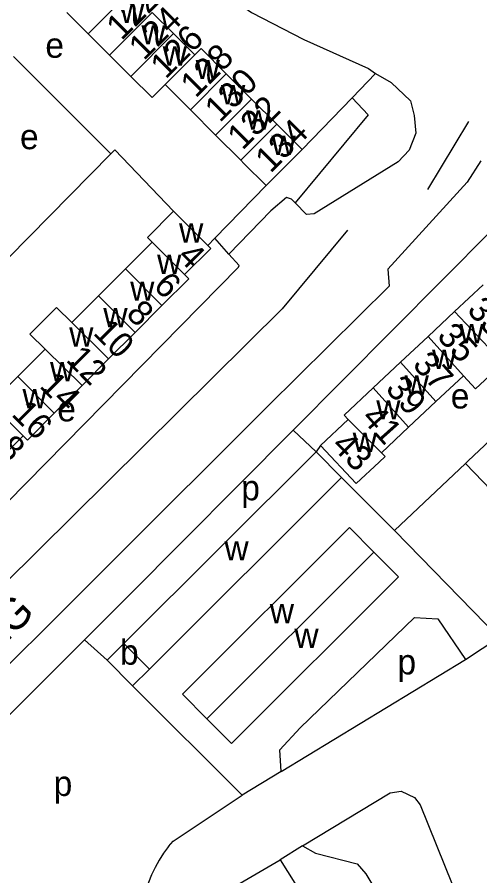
# Model space of a CAD drawing. Extents: x 159261 to 160849, y 382514 to 384534.
# Drawn here: x 160281.9 to 160355.7, y 383033.8 to 383170.7 of the extents above; entities that cross this region are included whole.
import ezdxf

# ---------------------------------------------------------------- set-up
doc = ezdxf.new("R2010")
doc.units = 0
for name, color, linetype in [('BLT_Basislijn', 7, 'Continuous'), ('BLT_Bebouwing', 7, 'Continuous'), ('BLT_Centroide', 7, 'Continuous'), ('BLT_Huisnummer', 7, 'Continuous'), ('BLT_Huisnummer_ tussenligend', 7, 'Continuous'), ('BLT_Onderverdeling_panden', 7, 'Continuous'), ('BLT_Straatnaam', 7, 'Continuous')]:
    doc.layers.add(name, color=color, linetype=linetype)

msp = doc.modelspace()

# ---------------------------------------------------------------- linework, layer by layer
at = {"layer": 'BLT_Basislijn'}
for p, q in [((160296.87, 383148.92), (160281.34, 383164.4)), ((160339.03, 383161.72), (160335.3, 383157.85)), ((160335.3, 383157.85), (160327.34, 383149.59)), ((160353.86, 383154.07), (160347.31, 383143.2)), ((160313.41, 383135.45), (160321.61, 383143.85)), ((160312.31, 383134.31), (160313.41, 383135.45)), ((160315.65, 383132.91), (160313.41, 383135.45)), ((160325.92, 383104.86), (160299.73, 383078.5)), ((160329.56, 383101.41), (160325.92, 383104.86)), ((160330.26, 383102.43), (160329.56, 383101.41)), ((160342.09, 383088.85), (160353.4, 383099.54)), ((160353.4, 383099.54), (160362.12, 383090.42)), ((160333.64, 383097.32), (160342.09, 383088.85)), ((160358.68, 383071.8), (160342.09, 383088.85)), ((160299.73, 383078.5), (160292.66, 383071.45)), ((160292.66, 383071.45), (160224.44, 383003.38)), ((160296.25, 383068.17), (160292.66, 383071.45)), ((160353.4, 383068.31), (160358.68, 383071.8)), ((160324.02, 383050.46), (160353.4, 383068.31)), ((160317.78, 383046.67), (160300.32, 383064.08)), ((160324.02, 383050.46), (160317.78, 383046.67)), ((160327.4, 383038.58), (160323.85, 383036.39)), ((160315.53, 383031.53), (160323.85, 383036.39)), ((160323.85, 383036.39), (160327.34, 383030.79))]:
    msp.add_line(p, q, dxfattribs=at)
for points in [[(160232.88, 383210.68), (160232.16, 383211.37), (160228.59, 383214.89), (160237.6, 383223.81), (160244.03, 383230.11), (160249.64, 383235.64), (160297.74, 383187.93), (160303.17, 383183), (160305.86, 383180.84), (160319.29, 383171.45), (160327.62, 383167.15), (160337.92, 383162.53), (160339.03, 383161.72)], [(160339.03, 383161.72), (160341.54, 383160.27), (160344.6, 383157.34), (160345.2, 383154.99), (160345.45, 383152.22), (160344.38, 383149.48), (160342.63, 383147.63), (160329.26, 383139.35), (160328.06, 383139.21), (160326.23, 383141.08)], [(160335.3, 383157.85), (160337.88, 383155.1), (160326.23, 383141.08)], [(160353.4, 383099.54), (160353.83, 383099.95), (160407.94, 383150.82)], [(160296.87, 383148.92), (160297.47, 383149.52), (160306.86, 383139.76)], [(160229.6, 383079.85), (160257.76, 383109.21), (160296.87, 383148.92)], [(160355.84, 383147.78), (160353.62, 383144.38), (160340.98, 383130.53), (160341.2, 383127.83), (160321.87, 383108.69)], [(160326.23, 383141.08), (160325.63, 383141.7), (160324.86, 383141.92), (160322.37, 383139.8), (160315.65, 383132.91)], [(160363.08, 383142.41), (160357.58, 383136.72), (160325.92, 383104.86)], [(160334.55, 383136.76), (160324.14, 383124.2), (160229.84, 383030.77)], [(160247.61, 383061.63), (160249.56, 383062.08), (160317.22, 383130.85), (160317.32, 383131.11), (160315.65, 383132.91)], [(160203.53, 382990.28), (160202.85, 382990.76), (160202.85, 382993.78), (160211.42, 383003.04), (160240.74, 383031.83), (160241.16, 383032.1), (160244.98, 383032.15), (160245.93, 383032.94), (160321.87, 383108.69)], [(160324.02, 383050.46), (160323.79, 383053.92), (160327.01, 383057.43), (160345.24, 383075.02), (160348.98, 383074.77), (160353.4, 383068.31)], [(160327.4, 383038.58), (160341.36, 383047.07), (160343.11, 383047.32), (160345.27, 383046.33), (160346.13, 383045.12), (160353.93, 383025.89), (160370.26, 382983.18)], [(160306.03, 383038.52), (160306.81, 383039.36), (160317.78, 383046.67)], [(160306.03, 383038.52), (160305.26, 383037.45), (160304.55, 383036.33), (160303.91, 383035.17), (160303.34, 383033.97), (160302.85, 383032.74), (160302.43, 383031.49), (160302.08, 383030.21), (160301.82, 383028.91), (160301.63, 383027.6), (160301.59, 383027.15)], [(160327.4, 383038.58), (160329.45, 383037.45), (160336.14, 383035.73), (160337.5, 383034.16), (160361.73, 382993.94), (160361.67, 382992.6), (160359.41, 382991.26), (160359.25, 382990.43), (160364.88, 382981.05), (160365.71, 382980.62), (160370.26, 382983.18)]]:
    msp.add_lwpolyline(points, dxfattribs=at)
at = {"layer": 'BLT_Bebouwing'}
for p, q in [((160289.85, 383171.43), (160293.24, 383168.04)), ((160306.84, 383168.07), (160303.45, 383171.46)), ((160293.24, 383168.04), (160296.64, 383164.65)), ((160310.24, 383164.68), (160306.84, 383168.07)), ((160296.64, 383164.65), (160300.03, 383161.25)), ((160310.24, 383164.68), (160311.24, 383165.68)), ((160315.26, 383161.66), (160311.24, 383165.68)), ((160319.29, 383157.64), (160315.26, 383161.66)), ((160305.51, 383159.95), (160309.53, 383155.93)), ((160323.31, 383153.61), (160319.29, 383157.64)), ((160309.53, 383155.93), (160313.56, 383151.9)), ((160327.34, 383149.59), (160323.31, 383153.61)), ((160313.56, 383151.9), (160317.58, 383147.88)), ((160321.61, 383143.85), (160327.34, 383149.59)), ((160306.86, 383139.76), (160302.69, 383135.59)), ((160303.45, 383134.83), (160299.17, 383130.55)), ((160302.69, 383135.59), (160303.45, 383134.83)), ((160299.17, 383130.55), (160294.88, 383126.26)), ((160356.17, 383128.02), (160351.65, 383123.79)), ((160294.88, 383126.26), (160290.63, 383122.02)), ((160305, 383124.71), (160300.71, 383120.42)), ((160351.65, 383123.79), (160347.41, 383119.81)), ((160300.71, 383120.42), (160296.5, 383116.22)), ((160347.41, 383119.81), (160343.03, 383115.71)), ((160286.38, 383117.77), (160282.02, 383113.4)), ((160296.5, 383116.22), (160292.27, 383111.99)), ((160343.03, 383115.71), (160338.66, 383111.6)), ((160282.02, 383113.4), (160277.86, 383109.25)), ((160353.05, 383113.52), (160348.67, 383109.41)), ((160292.27, 383111.99), (160287.84, 383107.57)), ((160348.67, 383109.41), (160344.3, 383105.31)), ((160344.3, 383105.31), (160339.98, 383101.26)), ((160282.86, 383103.98), (160278.86, 383099.98)), ((160329.56, 383101.41), (160298.95, 383070.87)), ((160333.64, 383097.32), (160329.56, 383101.41)), ((160303.02, 383066.78), (160333.64, 383097.32)), ((160296.25, 383068.17), (160298.95, 383070.87)), ((160300.32, 383064.08), (160296.25, 383068.17)), ((160303.02, 383066.78), (160300.32, 383064.08))]:
    msp.add_line(p, q, dxfattribs=at)
for points in [[(160300.03, 383161.25), (160303.42, 383157.86), (160305.51, 383159.95)], [(160317.58, 383147.88), (160318.07, 383147.39), (160321.61, 383143.85)], [(160312.31, 383134.31), (160309.24, 383137.38), (160306.86, 383139.76)], [(160312.31, 383134.31), (160312.77, 383133.84), (160308.6, 383129.68)], [(160308.6, 383129.68), (160309.29, 383128.99), (160305, 383124.71)], [(160290.63, 383122.02), (160288.21, 383124.41), (160283.95, 383120.16), (160286.38, 383117.77)], [(160359.37, 383115.55), (160354.99, 383111.45), (160353.05, 383113.52)], [(160338.66, 383111.6), (160334.02, 383107.25), (160334.67, 383106.56)], [(160287.84, 383107.57), (160283.56, 383103.28), (160282.86, 383103.98)], [(160334.67, 383106.56), (160330.26, 383102.43)], [(160330.26, 383102.43), (160335.98, 383096.34), (160339.62, 383099.76), (160340.56, 383100.64), (160339.98, 383101.26)], [(160338.79, 383085.41), (160334.87, 383089.34), (160308.26, 383062.79), (160312.18, 383058.86)], [(160312.18, 383058.86), (160316.1, 383054.93), (160342.71, 383081.48), (160338.79, 383085.41)]]:
    msp.add_lwpolyline(points, dxfattribs=at)
at = {"layer": 'BLT_Onderverdeling_panden'}
for p, q in [((160293.24, 383168.04), (160300.05, 383174.85)), ((160296.64, 383164.65), (160303.45, 383171.46)), ((160300.03, 383161.25), (160306.84, 383168.07)), ((160305.51, 383159.95), (160310.24, 383164.68)), ((160309.53, 383155.93), (160315.26, 383161.66)), ((160313.56, 383151.9), (160319.29, 383157.64)), ((160317.58, 383147.88), (160323.31, 383153.61)), ((160303.45, 383134.83), (160308.6, 383129.68)), ((160305, 383124.71), (160299.17, 383130.55)), ((160300.71, 383120.42), (160294.88, 383126.26)), ((160351.65, 383123.79), (160359.37, 383115.55)), ((160296.5, 383116.22), (160290.63, 383122.02)), ((160347.41, 383119.81), (160353.05, 383113.52)), ((160292.27, 383111.99), (160286.38, 383117.77)), ((160343.03, 383115.71), (160348.67, 383109.41)), ((160287.84, 383107.57), (160282.02, 383113.4)), ((160338.66, 383111.6), (160344.3, 383105.31)), ((160334.67, 383106.56), (160339.98, 383101.26)), ((160338.79, 383085.41), (160312.18, 383058.86)), ((160298.95, 383070.87), (160303.02, 383066.78))]:
    msp.add_line(p, q, dxfattribs=at)
msp.add_lwpolyline([(160277.86, 383109.25), (160277.73, 383109.12), (160282.86, 383103.98)], dxfattribs=at)

# ---------------------------------------------------------------- texts
at = {"layer": 'BLT_Centroide'}
for s, p in [('w', (160298.34, 383169.75)), ('w', (160301.73, 383166.34)), ('e', (160286.42, 383164.22)), ('w', (160305.12, 383162.97)), ('w', (160310.38, 383160.81)), ('w', (160314.41, 383156.78)), ('w', (160318.44, 383152.75)), ('e', (160282.38, 383149.64)), ('w', (160322.46, 383148.72)), ('w', (160307.73, 383134.73)), ('w', (160304.23, 383129.77)), ('w', (160299.94, 383125.48)), ('w', (160295.66, 383121.25)), ('w', (160290.22, 383118.19)), ('w', (160352.42, 383118.72)), ('w', (160348.05, 383114.61)), ('w', (160287.16, 383112.66)), ('w', (160343.67, 383110.5)), ('w', (160282.78, 383108.34)), ('e', (160351.03, 383108.31)), ('e', (160288.32, 383106.26)), ('w', (160339.16, 383106.56)), ('w', (160335.41, 383101.38)), ('p', (160317.64, 383093.68)), ('w', (160314.96, 383084.09)), ('w', (160322.19, 383074.09)), ('w', (160326.11, 383070.16)), ('b', (160298.31, 383067.48)), ('p', (160342.53, 383065.93)), ('p', (160287.74, 383046.55))]:
    msp.add_text(s, height=4, dxfattribs=at).set_placement(p)
at = {"layer": 'BLT_Huisnummer'}
for s, rotation, p in [('122', 45.0126, (160298.56, 383166.86)), ('126', 45.01, (160305.6, 383160.68)), ('130', 45.01, (160314.25, 383153.77)), ('134', 45.01, (160322.3, 383145.71)), ('4', 314.9754, (160307.32, 383132.35)), ('8', 314.9754, (160299.12, 383123.2)), ('33', 311.8627, (160353.47, 383123.9)), ('12', 314.9705, (160289.54, 383115.95)), ('37', 311.8597, (160344.79, 383115.19)), ('16', 314.9756, (160280.87, 383107.29)), ('43', 314.9298, (160331.86, 383102.23))]:
    msp.add_text(s, height=4, rotation=rotation, dxfattribs=at).set_placement(p)
at = {"layer": 'BLT_Huisnummer_ tussenligend'}
for s, rotation, p in [('124', 45.0126, (160302.14, 383163.65)), ('128', 45.01, (160310.39, 383157.69)), ('132', 45.01, (160317.85, 383149.38)), ('6', 314.9754, (160303.47, 383127.66)), ('10', 314.9754, (160293.89, 383120.22)), ('35', 311.8627, (160348.68, 383119.74)), ('14', 314.9705, (160285.34, 383111.77)), ('39', 311.8597, (160340.48, 383111.35)), ('41', 311.8597, (160336.63, 383106.7)), ('18', 314.9756, (160276.52, 383103.77))]:
    msp.add_text(s, height=4, rotation=rotation, dxfattribs=at).set_placement(p)
at = {"layer": 'BLT_Straatnaam'}
msp.add_text('JOZEF ELIASWEG', height=5, rotation=44.9279, dxfattribs=at).set_placement((160243.95, 383034.73))

doc.saveas('drawing.dxf')
